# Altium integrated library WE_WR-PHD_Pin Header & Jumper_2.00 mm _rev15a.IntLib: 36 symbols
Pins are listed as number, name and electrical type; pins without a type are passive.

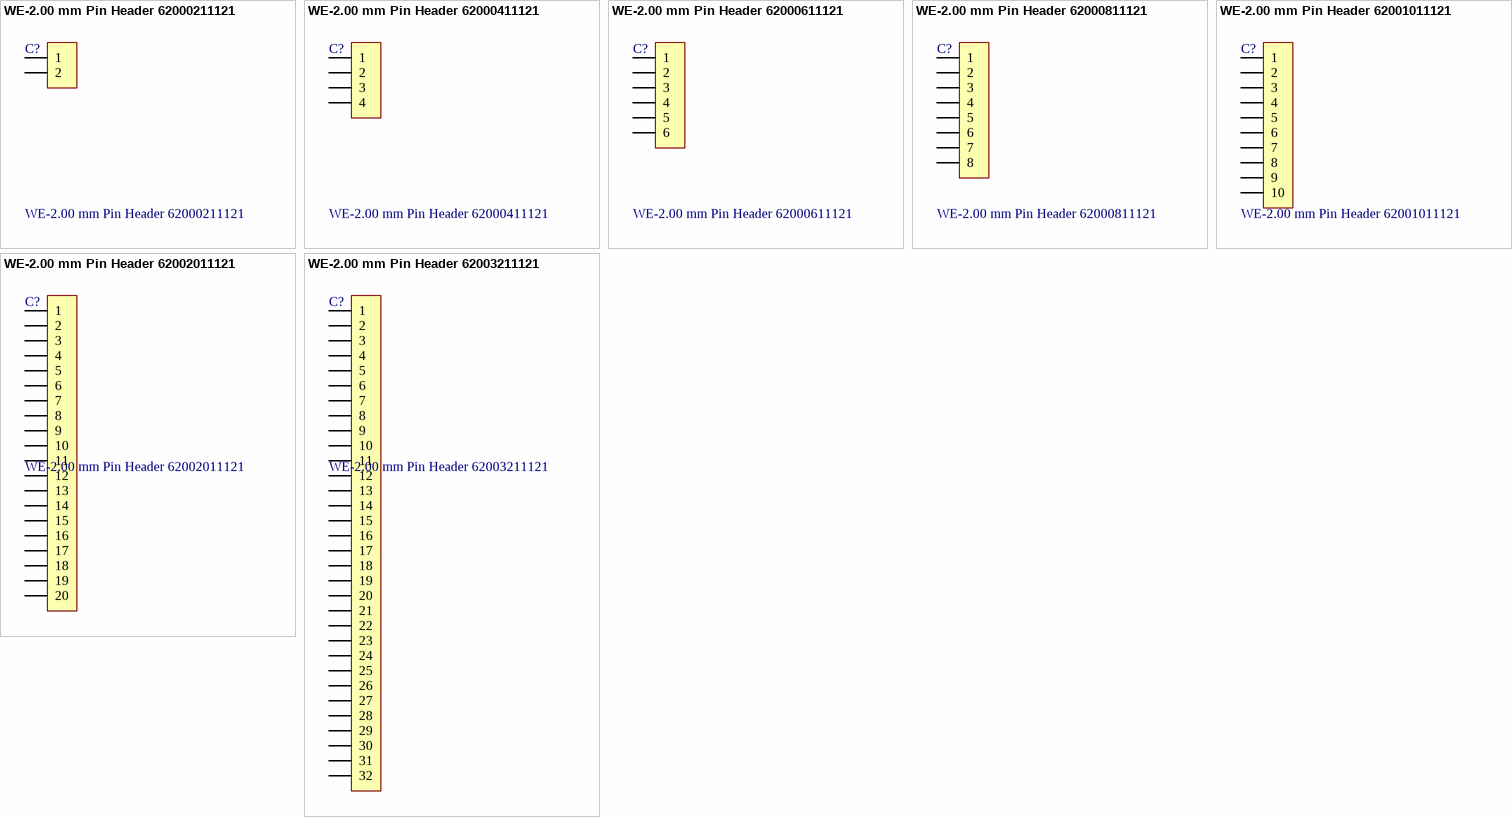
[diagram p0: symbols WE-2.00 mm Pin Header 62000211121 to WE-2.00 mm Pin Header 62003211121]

## WE-2.00 mm Pin Header 62000211121
designator C?
WR-PHD 2.00 mm Pin Header; Manufacturer: Würth Elektronik eiSos GmbH; ComponentLink1 Description: Manufacturer; ComponentLink2 Description: Datasheet; NoPins: 02
footprint 62000211121 (2 pins, 1 row, straight, gold plating)
pins: 1, 2

## WE-2.00 mm Pin Header 62000411121
designator C?
WR-PHD 2.00 mm Pin Header; Manufacturer: Würth Elektronik eiSos GmbH; ComponentLink1 Description: Manufacturer; ComponentLink2 Description: Datasheet; NoPins: 04
footprint 62000411121 (4 pins, 1 row, straight, gold plating)
pins: 1, 2, 3, 4

## WE-2.00 mm Pin Header 62000611121
designator C?
WR-PHD 2.00 mm Pin Header; Manufacturer: Würth Elektronik eiSos GmbH; ComponentLink1 Description: Manufacturer; ComponentLink2 Description: Datasheet; NoPins: 06
footprint 62000611121 (6 pins, 1 row, straight, gold plating)
pins: 1, 2, 3, 4, 5, 6

## WE-2.00 mm Pin Header 62000811121
designator C?
WR-PHD 2.00 mm Pin Header; Manufacturer: Würth Elektronik eiSos GmbH; ComponentLink1 Description: Manufacturer; ComponentLink2 Description: Datasheet; NoPins: 08
footprint 62000811121 (8 pins, 1 row, straight, gold plating)
pins: 1, 2, 3, 4, 5, 6, 7, 8

## WE-2.00 mm Pin Header 62001011121
designator C?
WR-PHD 2.00 mm Pin Header; Manufacturer: Würth Elektronik eiSos GmbH; ComponentLink1 Description: Manufacturer; ComponentLink2 Description: Datasheet; NoPins: 10
footprint 62001011121 (10 pins, 1 row, straight, gold plating)
pins: 1, 2, 3, 4, 5, 6, 7, 8, 9, 10

## WE-2.00 mm Pin Header 62002011121
designator C?
WR-PHD 2.00 mm Pin Header; Manufacturer: Würth Elektronik eiSos GmbH; ComponentLink1 Description: Manufacturer; ComponentLink2 Description: Datasheet; NoPins: 20
footprint 62002011121 (20 pins, 1 row, straight, gold plating)
pins: 1, 2, 3, 4, 5, 6, 7, 8, 9, 10, 11, 12, 13, 14, 15, 16, 17, 18, 19, 20

## WE-2.00 mm Pin Header 62003211121
designator C?
WR-PHD 2.00 mm Pin Header; Manufacturer: Würth Elektronik eiSos GmbH; ComponentLink1 Description: Manufacturer; ComponentLink2 Description: Datasheet; NoPins: 32
footprint 62003211121 (32 pins, 1 row, straight, gold plating)
pins: 1, 2, 3, 4, 5, 6, 7, 8, 9, 10, 11, 12, 13, 14, 15, 16, 17, 18, 19, 20, 21, 22, 23, 24, 25, 26, 27, 28, 29, 30, 31, 32


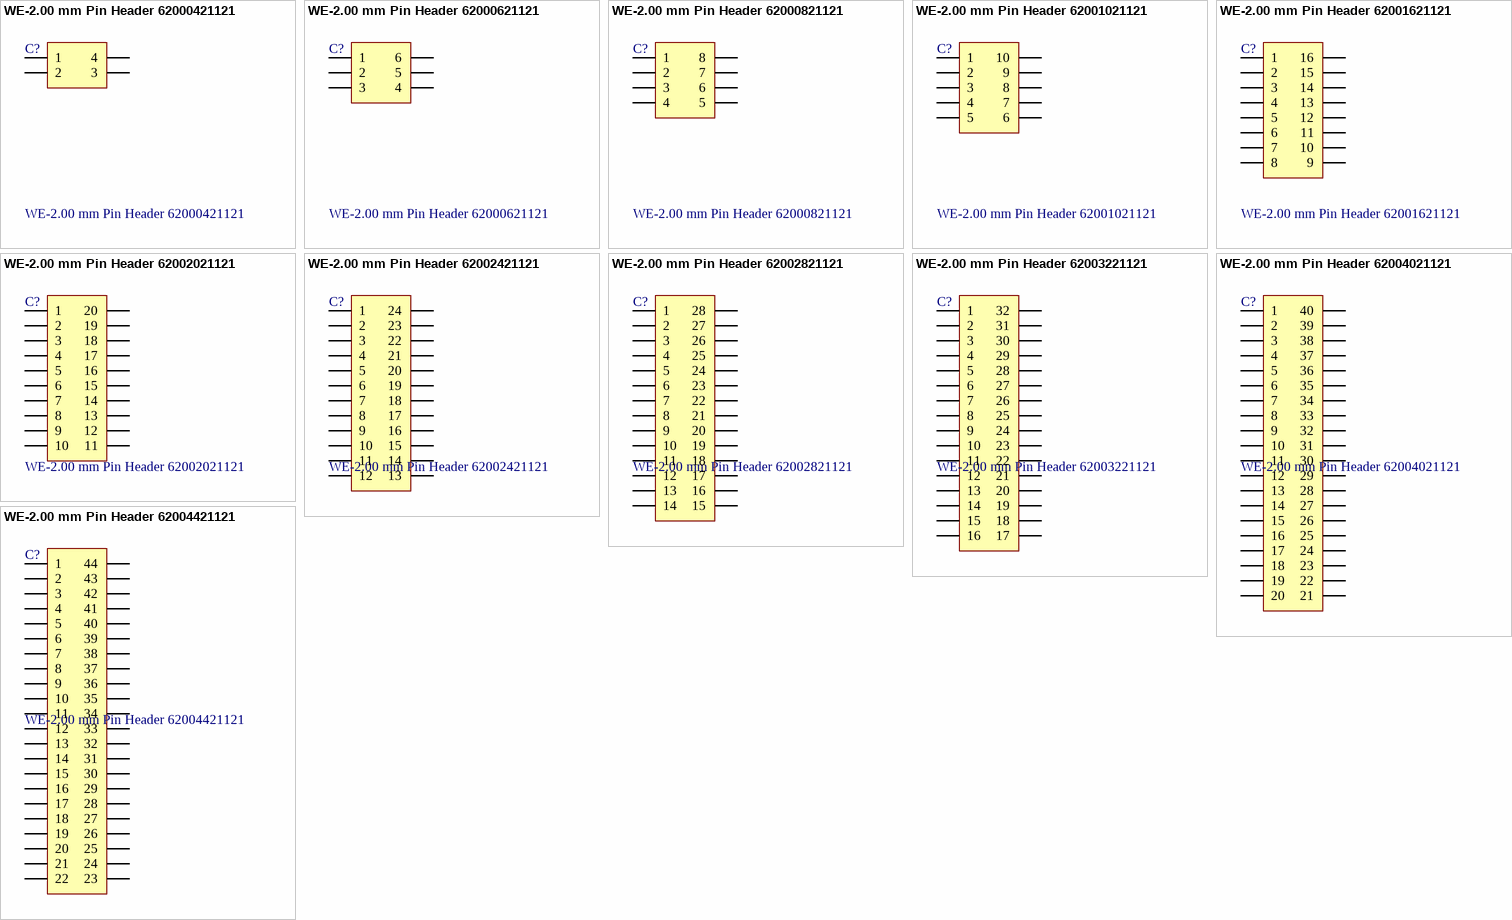
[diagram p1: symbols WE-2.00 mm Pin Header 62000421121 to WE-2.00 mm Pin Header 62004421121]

## WE-2.00 mm Pin Header 62000421121
designator C?
WR-PHD 2.00 mm Dual Pin Header; Manufacturer: Würth Elektronik eiSos GmbH; ComponentLink1 Description: Manufacturer; ComponentLink2 Description: Datasheet; NoPins: 04
footprint 62000421121 (4 pins, dual row, straight, gold plating)
pins: 1, 2, 3, 4

## WE-2.00 mm Pin Header 62000621121
designator C?
WR-PHD 2.00 mm Dual Pin Header; Manufacturer: Würth Elektronik eiSos GmbH; ComponentLink1 Description: Manufacturer; ComponentLink2 Description: Datasheet; NoPins: 06
footprint 62000621121 (6 pins, dual row, straight, gold plating)
pins: 1, 2, 3, 4, 5, 6

## WE-2.00 mm Pin Header 62000821121
designator C?
WR-PHD 2.00 mm Dual Pin Header; Manufacturer: Würth Elektronik eiSos GmbH; ComponentLink1 Description: Manufacturer; ComponentLink2 Description: Datasheet; NoPins: 08
footprint 62000821121 (8 pins, dual row, straight, gold plating)
pins: 1, 2, 3, 4, 5, 6, 7, 8

## WE-2.00 mm Pin Header 62001021121
designator C?
WR-PHD 2.00 mm Dual Pin Header; Manufacturer: Würth Elektronik eiSos GmbH; ComponentLink1 Description: Manufacturer; ComponentLink2 Description: Datasheet; NoPins: 10
footprint 62001021121 (10 pins, dual row, straight, gold plating)
pins: 1, 2, 3, 4, 5, 6, 7, 8, 9, 10

## WE-2.00 mm Pin Header 62001621121
designator C?
WR-PHD 2.00 mm Dual Pin Header; Manufacturer: Würth Elektronik eiSos GmbH; ComponentLink1 Description: Manufacturer; ComponentLink2 Description: Datasheet; NoPins: 16
footprint 62001621121 (16 pins, dual row, straight, gold plating)
pins: 1, 2, 3, 4, 5, 6, 7, 8, 9, 10, 11, 12, 13, 14, 15, 16

## WE-2.00 mm Pin Header 62002021121
designator C?
WR-PHD 2.00 mm Dual Pin Header; Manufacturer: Würth Elektronik eiSos GmbH; ComponentLink1 Description: Manufacturer; ComponentLink2 Description: Datasheet; NoPins: 20
footprint 62002021121 (20 pins, dual row, straight, gold plating)
pins: 1, 2, 3, 4, 5, 6, 7, 8, 9, 10, 11, 12, 13, 14, 15, 16, 17, 18, 19, 20

## WE-2.00 mm Pin Header 62002421121
designator C?
WR-PHD 2.00 mm Dual Pin Header; Manufacturer: Würth Elektronik eiSos GmbH; ComponentLink1 Description: Manufacturer; ComponentLink2 Description: Datasheet; NoPins: 24
footprint 62002421121 (24 pins, dual row, straight, gold plating)
pins: 1, 2, 3, 4, 5, 6, 7, 8, 9, 10, 11, 12, 13, 14, 15, 16, 17, 18, 19, 20, 21, 22, 23, 24

## WE-2.00 mm Pin Header 62002821121
designator C?
WR-PHD 2.00 mm Dual Pin Header; Manufacturer: Würth Elektronik eiSos GmbH; ComponentLink1 Description: Manufacturer; ComponentLink2 Description: Datasheet; NoPins: 28
footprint 62002821121 (28 pins, dual row, straight, gold plating)
pins: 1, 2, 3, 4, 5, 6, 7, 8, 9, 10, 11, 12, 13, 14, 15, 16, 17, 18, 19, 20, 21, 22, 23, 24, 25, 26, 27, 28

## WE-2.00 mm Pin Header 62003221121
designator C?
WR-PHD 2.00 mm Dual Pin Header; Manufacturer: Würth Elektronik eiSos GmbH; ComponentLink1 Description: Manufacturer; ComponentLink2 Description: Datasheet; NoPins: 32
footprint 62003221121 (32 pins, dual row, straight, gold plating)
pins: 1, 2, 3, 4, 5, 6, 7, 8, 9, 10, 11, 12, 13, 14, 15, 16, 17, 18, 19, 20, 21, 22, 23, 24, 25, 26, 27, 28, 29, 30, 31, 32

## WE-2.00 mm Pin Header 62004021121
designator C?
WR-PHD 2.00 mm Dual Pin Header; Manufacturer: Würth Elektronik eiSos GmbH; ComponentLink1 Description: Manufacturer; ComponentLink2 Description: Datasheet; NoPins: 40
footprint 62004021121 (40 pins, dual row, straight, gold plating)
pins: 1, 2, 3, 4, 5, 6, 7, 8, 9, 10, 11, 12, 13, 14, 15, 16, 17, 18, 19, 20, 21, 22, 23, 24, 25, 26, 27, 28, 29, 30, 31, 32, 33, 34, 35, 36, 37, 38, 39, 40

## WE-2.00 mm Pin Header 62004421121
designator C?
WR-PHD 2.00 mm Dual Pin Header; Manufacturer: Würth Elektronik eiSos GmbH; ComponentLink1 Description: Manufacturer; ComponentLink2 Description: Datasheet; NoPins: 44
footprint 62004421121 (44pins, dual row, straight, gold plating)
pins: 1, 2, 3, 4, 5, 6, 7, 8, 9, 10, 11, 12, 13, 14, 15, 16, 17, 18, 19, 20, 21, 22, 23, 24, 25, 26, 27, 28, 29, 30, 31, 32, 33, 34, 35, 36, 37, 38, 39, 40, 41, 42, 43, 44


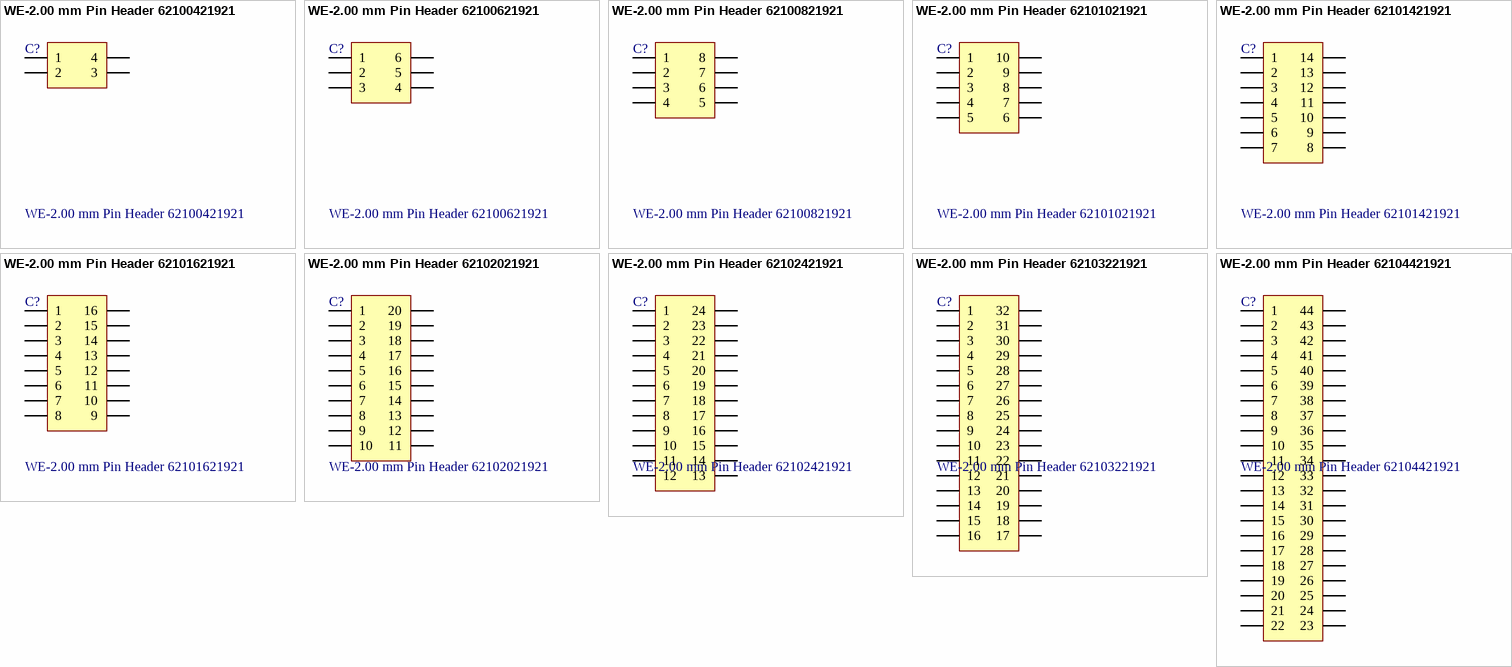
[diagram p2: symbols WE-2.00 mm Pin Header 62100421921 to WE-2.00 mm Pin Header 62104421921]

## WE-2.00 mm Pin Header 62100421921
designator C?
WR-PHD 2.00 mm Dual SMT Pin Header; Manufacturer: Würth Elektronik eiSos GmbH; ComponentLink1 Description: Manufacturer; ComponentLink2 Description: Datasheet; NoPins: 04
footprint 62100421921 (SMT, 4 pins, dual row, straight, gold plating)
pins: 1, 2, 3, 4

## WE-2.00 mm Pin Header 62100621921
designator C?
WR-PHD 2.00 mm Dual SMT Pin Header; Manufacturer: Würth Elektronik eiSos GmbH; ComponentLink1 Description: Manufacturer; ComponentLink2 Description: Datasheet; NoPins: 06
footprint 62100621921 (SMT, 6 pins, dual row, straight, gold plating)
pins: 1, 2, 3, 4, 5, 6

## WE-2.00 mm Pin Header 62100821921
designator C?
WR-PHD 2.00 mm Dual SMT Pin Header; Manufacturer: Würth Elektronik eiSos GmbH; ComponentLink1 Description: Manufacturer; ComponentLink2 Description: Datasheet; NoPins: 08
footprint 62100821921 (SMT, 8 pins, dual row, straight, gold plating)
pins: 1, 2, 3, 4, 5, 6, 7, 8

## WE-2.00 mm Pin Header 62101021921
designator C?
WR-PHD 2.00 mm Dual SMT Pin Header; Manufacturer: Würth Elektronik eiSos GmbH; ComponentLink1 Description: Manufacturer; ComponentLink2 Description: Datasheet; NoPins: 10
footprint 62101021921 (SMT, 10 pins, dual row, straight, gold plating)
pins: 1, 2, 3, 4, 5, 6, 7, 8, 9, 10

## WE-2.00 mm Pin Header 62101421921
designator C?
WR-PHD 2.00 mm Dual SMT Pin Header; Manufacturer: Würth Elektronik eiSos GmbH; ComponentLink1 Description: Manufacturer; ComponentLink2 Description: Datasheet; NoPins: 14
footprint 62101421921 (SMT, 14 pins, dual row, straight, gold plating)
pins: 1, 2, 3, 4, 5, 6, 7, 8, 9, 10, 11, 12, 13, 14

## WE-2.00 mm Pin Header 62101621921
designator C?
WR-PHD 2.00 mm Dual SMT Pin Header; Manufacturer: Würth Elektronik eiSos GmbH; ComponentLink1 Description: Manufacturer; ComponentLink2 Description: Datasheet; NoPins: 16
footprint 62101621921 (SMT, 16 pins, dual row, straight, gold plating)
pins: 1, 2, 3, 4, 5, 6, 7, 8, 9, 10, 11, 12, 13, 14, 15, 16

## WE-2.00 mm Pin Header 62102021921
designator C?
WR-PHD 2.00 mm Dual SMT Pin Header; Manufacturer: Würth Elektronik eiSos GmbH; ComponentLink1 Description: Manufacturer; ComponentLink2 Description: Datasheet; NoPins: 20
footprint 62102021921 (SMT, 20 pins, dual row, straight, gold plating)
pins: 1, 2, 3, 4, 5, 6, 7, 8, 9, 10, 11, 12, 13, 14, 15, 16, 17, 18, 19, 20

## WE-2.00 mm Pin Header 62102421921
designator C?
WR-PHD 2.00 mm Dual SMT Pin Header; Manufacturer: Würth Elektronik eiSos GmbH; ComponentLink1 Description: Manufacturer; ComponentLink2 Description: Datasheet; NoPins: 24
footprint 62102421921 (SMT, 24 pins, dual row, straight, gold plating)
pins: 1, 2, 3, 4, 5, 6, 7, 8, 9, 10, 11, 12, 13, 14, 15, 16, 17, 18, 19, 20, 21, 22, 23, 24

## WE-2.00 mm Pin Header 62103221921
designator C?
WR-PHD 2.00 mm Dual SMT Pin Header; Manufacturer: Würth Elektronik eiSos GmbH; ComponentLink1 Description: Manufacturer; ComponentLink2 Description: Datasheet; NoPins: 32
footprint 62103221921 (SMT, 32 pins, dual row, straight, gold plating)
pins: 1, 2, 3, 4, 5, 6, 7, 8, 9, 10, 11, 12, 13, 14, 15, 16, 17, 18, 19, 20, 21, 22, 23, 24, 25, 26, 27, 28, 29, 30, 31, 32

## WE-2.00 mm Pin Header 62104421921
designator C?
WR-PHD 2.00 mm Dual SMT Pin Header; Manufacturer: Würth Elektronik eiSos GmbH; ComponentLink1 Description: Manufacturer; ComponentLink2 Description: Datasheet; NoPins: 44
footprint 62104421921 (SMT, 44 pins, dual row, straight, gold plating)
pins: 1, 2, 3, 4, 5, 6, 7, 8, 9, 10, 11, 12, 13, 14, 15, 16, 17, 18, 19, 20, 21, 22, 23, 24, 25, 26, 27, 28, 29, 30, 31, 32, 33, 34, 35, 36, 37, 38, 39, 40, 41, 42, 43, 44


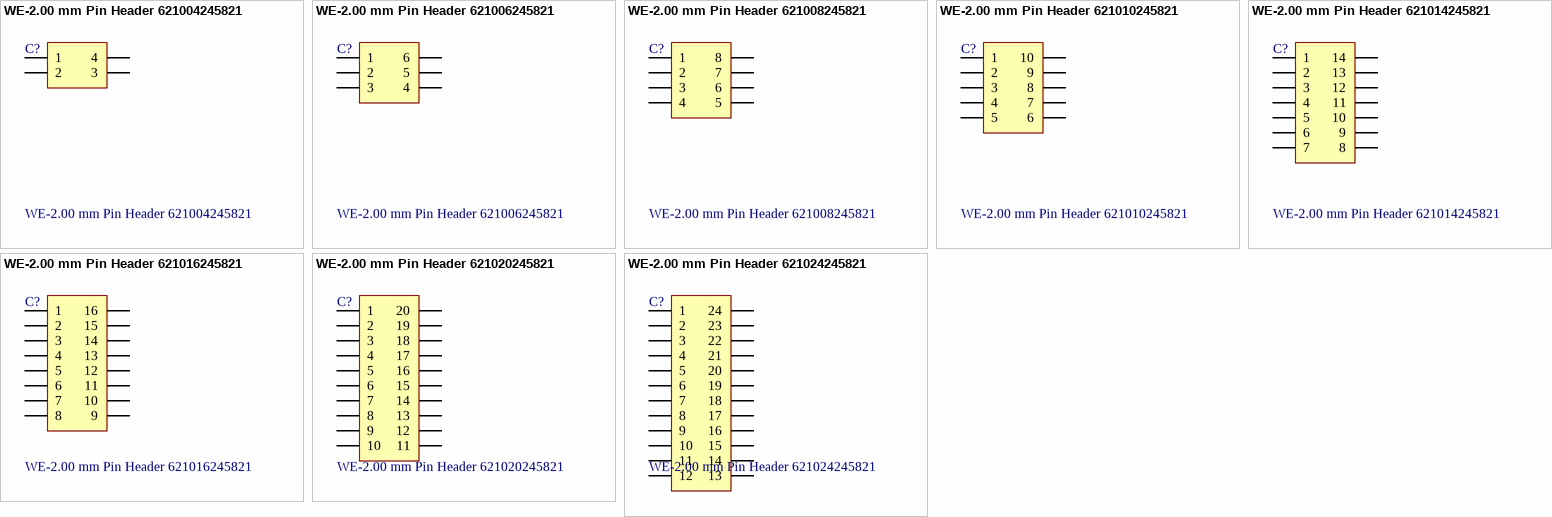
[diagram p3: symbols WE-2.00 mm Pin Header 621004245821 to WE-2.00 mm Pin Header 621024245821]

## WE-2.00 mm Pin Header 621004245821
designator C?
WR-PHD 2.00 mm Dual SMT Pin Header Low Profile; Manufacturer: Würth Elektronik eiSos GmbH; ComponentLink1 Description: Manufacturer; ComponentLink2 Description: Datasheet; NoPins: 04
footprint 621004245821 (SMT, 4 pins, dual row, straight, gold plating, 2mm long)
pins: 1, 2, 3, 4

## WE-2.00 mm Pin Header 621006245821
designator C?
WR-PHD 2.00 mm Dual SMT Pin Header Low Profile; Manufacturer: Würth Elektronik eiSos GmbH; ComponentLink1 Description: Manufacturer; ComponentLink2 Description: Datasheet; NoPins: 06
footprint 621006245821 (SMT, 6 pins, dual row, straight, gold plating 2mm long)
pins: 1, 2, 3, 4, 5, 6

## WE-2.00 mm Pin Header 621008245821
designator C?
WR-PHD 2.00 mm Dual SMT Pin Header Low Profile; Manufacturer: Würth Elektronik eiSos GmbH; ComponentLink1 Description: Manufacturer; ComponentLink2 Description: Datasheet; NoPins: 08
footprint 621008245821 (SMT, 8 pins, dual row, straight, gold plating 2mm long)
pins: 1, 2, 3, 4, 5, 6, 7, 8

## WE-2.00 mm Pin Header 621010245821
designator C?
WR-PHD 2.00 mm Dual SMT Pin Header Low Profile; Manufacturer: Würth Elektronik eiSos GmbH; ComponentLink1 Description: Manufacturer; ComponentLink2 Description: Datasheet; NoPins: 10
footprint 621010245821 (SMT, 10 pins, dual row, straight, gold plating 2mm long)
pins: 1, 2, 3, 4, 5, 6, 7, 8, 9, 10

## WE-2.00 mm Pin Header 621014245821
designator C?
WR-PHD 2.00 mm Dual SMT Pin Header Low Profile; Manufacturer: Würth Elektronik eiSos GmbH; ComponentLink1 Description: Manufacturer; ComponentLink2 Description: Datasheet; NoPins: 14
footprint 621014245821 (SMT, 14 pins, dual row, straight, gold plating 2mm long)
pins: 1, 2, 3, 4, 5, 6, 7, 8, 9, 10, 11, 12, 13, 14

## WE-2.00 mm Pin Header 621016245821
designator C?
WR-PHD 2.00 mm Dual SMT Pin Header Low Profile; Manufacturer: Würth Elektronik eiSos GmbH; ComponentLink1 Description: Manufacturer; ComponentLink2 Description: Datasheet; NoPins: 16
footprint 621016245821 (SMT, 16 pins, dual row, straight, gold plating 2mm long)
pins: 1, 2, 3, 4, 5, 6, 7, 8, 9, 10, 11, 12, 13, 14, 15, 16

## WE-2.00 mm Pin Header 621020245821
designator C?
WR-PHD 2.00 mm Dual SMT Pin Header Low Profile; Manufacturer: Würth Elektronik eiSos GmbH; ComponentLink1 Description: Manufacturer; ComponentLink2 Description: Datasheet; NoPins: 20
footprint 621020245821 (SMT, 20 pins, dual row, straight, gold plating 2mm long)
pins: 1, 2, 3, 4, 5, 6, 7, 8, 9, 10, 11, 12, 13, 14, 15, 16, 17, 18, 19, 20

## WE-2.00 mm Pin Header 621024245821
designator C?
WR-PHD 2.00 mm Dual SMT Pin Header Low Profile; Manufacturer: Würth Elektronik eiSos GmbH; ComponentLink1 Description: Manufacturer; ComponentLink2 Description: Datasheet; NoPins: 24
footprint 621024245821 (SMT, 24 pins, dual row, straight, gold plating 2mm long)
pins: 1, 2, 3, 4, 5, 6, 7, 8, 9, 10, 11, 12, 13, 14, 15, 16, 17, 18, 19, 20, 21, 22, 23, 24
